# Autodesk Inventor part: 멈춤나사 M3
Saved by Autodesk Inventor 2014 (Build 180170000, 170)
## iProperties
Created: 2026-09
Part Number: 멈춤나사 M3
Material: 일반
Document SubType Name: Modeling
Designer: dg
Density: 1 g/cm^3
Appearance: 기본값
Author: dg
Author: jhkim
Description: 6각 소켓 머리 없는 멈춤 나사
Creation Date: 2026-08-27
Sending System: Autodesk Inventor 2027
Preprocessor: ST-DEVELOPER v20.1
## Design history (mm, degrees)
node "멈춤나사 M31"
body "Solid1"
node "기준1"
